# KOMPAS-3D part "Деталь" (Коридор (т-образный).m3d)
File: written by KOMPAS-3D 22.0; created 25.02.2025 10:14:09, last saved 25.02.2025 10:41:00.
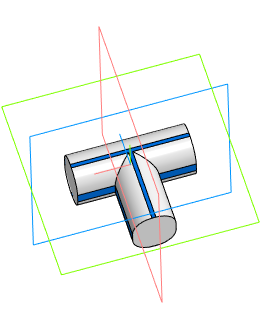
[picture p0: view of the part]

Document properties: Автор: Пользователь Windows; Полное имя файла: C:\Users\Student\Documents\Картошечка\База Сабнатика\Коридор\Коридор (т-образный).m3d

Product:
- Body: Тело 1
    Масса: 0.04792
- Part/product: Деталь
    Масса: 0.043049

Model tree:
1. Эскиз:1
2. Элемент выдавливания:1
     Расстояние 1 = 30
3. Эскиз:2
4. Элемент выдавливания:2
     Расстояние 1 = 20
